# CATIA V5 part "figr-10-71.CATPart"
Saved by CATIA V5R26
Part number: Part1
Bounding box of the stored display mesh (mm): x -45.985 to 45.985, y -45.985 to 45.985, z -55 to 3.515
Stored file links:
  D:\_Deepak\CATIA\CATIA V5-6R2016_Deepak\Resources\Part files\Partfiles\c10_catia_v5_6r2016_prt\figr-10-71.CATPart
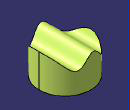
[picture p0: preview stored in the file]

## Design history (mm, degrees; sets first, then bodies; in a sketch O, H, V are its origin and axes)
Set1
  Sketch1 on xy-plane, origin (0, 0, 0), H (-1, 0, 0), V (0, -1, 0)
    circle A1 centre (0, 0) radius 45.985
  Extrude1: Element1 Sketch1, Lim1 56, Lim2 55, Direction xy-plane
  Sketch2 on zx-plane, origin (0, 0, 0), H (1, 0, 0), V (0, 0, -1)
    spline S1 through (-80.5635, 24.8913) (-73.6025, 19.8803) (-54.8525, -3.3629) (-35.1982, 19.8803) (-2.6271, -1.6506) (16.6996, 17.2854) (52.4104, -6.7877) (63.5409, 1.5862)
  Extrude2: Element1 Sketch2, Lim1 72, Lim2 69, Direction Sketch1.V
  Split1: ToCut Extrude1, Cutting Extrude2
  Trim1: Element1 Extrude1, Element2 Extrude2
  Trim2: Element1 Extrude1, Element2 Extrude2
Body1 (main body)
